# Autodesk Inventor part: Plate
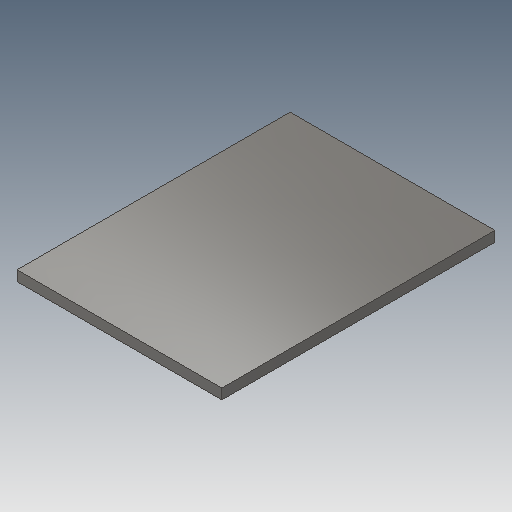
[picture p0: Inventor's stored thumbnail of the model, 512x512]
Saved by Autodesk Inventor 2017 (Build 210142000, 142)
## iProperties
Created: 2016-08
Part Number: Plate
Material: Steel, Carbon
Document SubType Name: Modeling
Designer: Gaurav
Density: 7.85 g/cm^3
Appearance: Semi-Polished
Author: Gaurav
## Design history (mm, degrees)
sketch "Sketch1"
  geometry: L1 (30, 40)-(-30, 40); L2 (-30, 40)-(-30, -40); L3 (-30, -40)-(30, -40); L4 (30, -40)-(30, 40); L5 (30, 40)-(-30, -40); L6 (-30, 40)-(30, -40); 1 further point
  constraints: 12 end point, 2 midpoint, 2 parallel, 1 horizontal, 1 perpendicular
  dimensions: "d0" = 60 distance of L3.end L2.end; "d1" = 80 distance of L2.end L1.end
extrude "Extrusion1" new body sketch "Sketch1" distance "d2" = 3; taper "d3" = 0 deg
body "Solid1"
